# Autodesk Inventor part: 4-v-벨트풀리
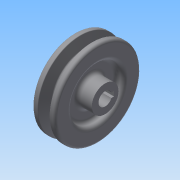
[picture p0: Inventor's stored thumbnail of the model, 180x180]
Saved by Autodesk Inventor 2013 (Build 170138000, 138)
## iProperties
Created: 2015-02
Part Number: 4-v-벨트풀리
Material: 일반
Document SubType Name: Modeling
Designer: Administrator
Density: 1 g/cm^3
Author: Administrator
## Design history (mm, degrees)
sketch "스케치1"
  geometry: L1 (0, 0)-(25, 0); L2 (0, 5.5)-(25, 5.5); L3 (25, 5.5)-(25, 11); L4 (25, 11)-(13, 11); L5 (13, 11)-(13, 21.5); L6 (13, 21.5)-(19, 21.5); L7 (19, 21.5)-(19, 35.2); L8 (19, 35.2)-(14.325, 35.2); L9 (11.574, 26.2)-(7.426, 26.2); L10 (4.675, 35.2)-(0, 35.2); L11 (0, 35.2)-(0, 21.5); L12 (0, 21.5)-(6, 21.5); L13 (6, 21.5)-(6, 11); L14 (6, 11)-(0, 11); L15 (0, 11)-(0, 5.5); L16 (4.675, 35.2)-(7.426, 26.2); L17 (11.574, 26.2)-(14.325, 35.2); 2 further points
  constraints: 34 end point, 8 parallel, 6 perpendicular, 4 equal length, 3 collinear, 2 point on line, 2 vertical alignment, 1 horizontal, 1 horizontal alignment
  dimensions: "d0" = 25 distance of L1.start L1.end; "d1" = 8 distance of point (13.5, 32.5) point (5.5, 32.5); "d2" = 34 deg angle of L17 L16; "d3" = 2.7 distance from line of L10 point (5.5, 32.5); "d4" = 65 diameter of point (5.5, 32.5) L1; "d5" = 6.3 distance from line of point (5.5, 32.5) L9; "d6" = 11 diameter of L2 L1; "d7" = 22 diameter of L14 L1; "d8" = 43 diameter of L12 L1; "d9" = 19 distance between parallel lines of L7 L11; "d10" = 6 distance of L11.end L12.end
revolve "회전1" sketch "스케치1" stored, may be unused: angle "d11" = 90 deg
sketch "스케치2"
  geometry: L1 (-2, 5.123)-(-2, 7.3); L2 (-2, 7.3)-(2, 7.3); L3 (2, 7.3)-(2, 5.123); A1 r 5.5 centre (0, 0) between (-2, 5.123) and (2, 5.123) reference; 1 further point
  constraints: 6 end point, 2 parallel, 2 point on circle, 1 midpoint, 1 perpendicular, 1 vertical alignment
  dimensions: "d12" = 4 distance of L1.end L2.end; "d14" = 12.8 dimension on A1 L2
extrude "돌출1" cut sketch "스케치2" stored distance "d15" = 10; taper "d16" = 0 deg
fillet "모깎기1" dims "d17" = 1, "d18" = 0.5, "d19" = 2, "d20" = 3
node "솔리드1"
